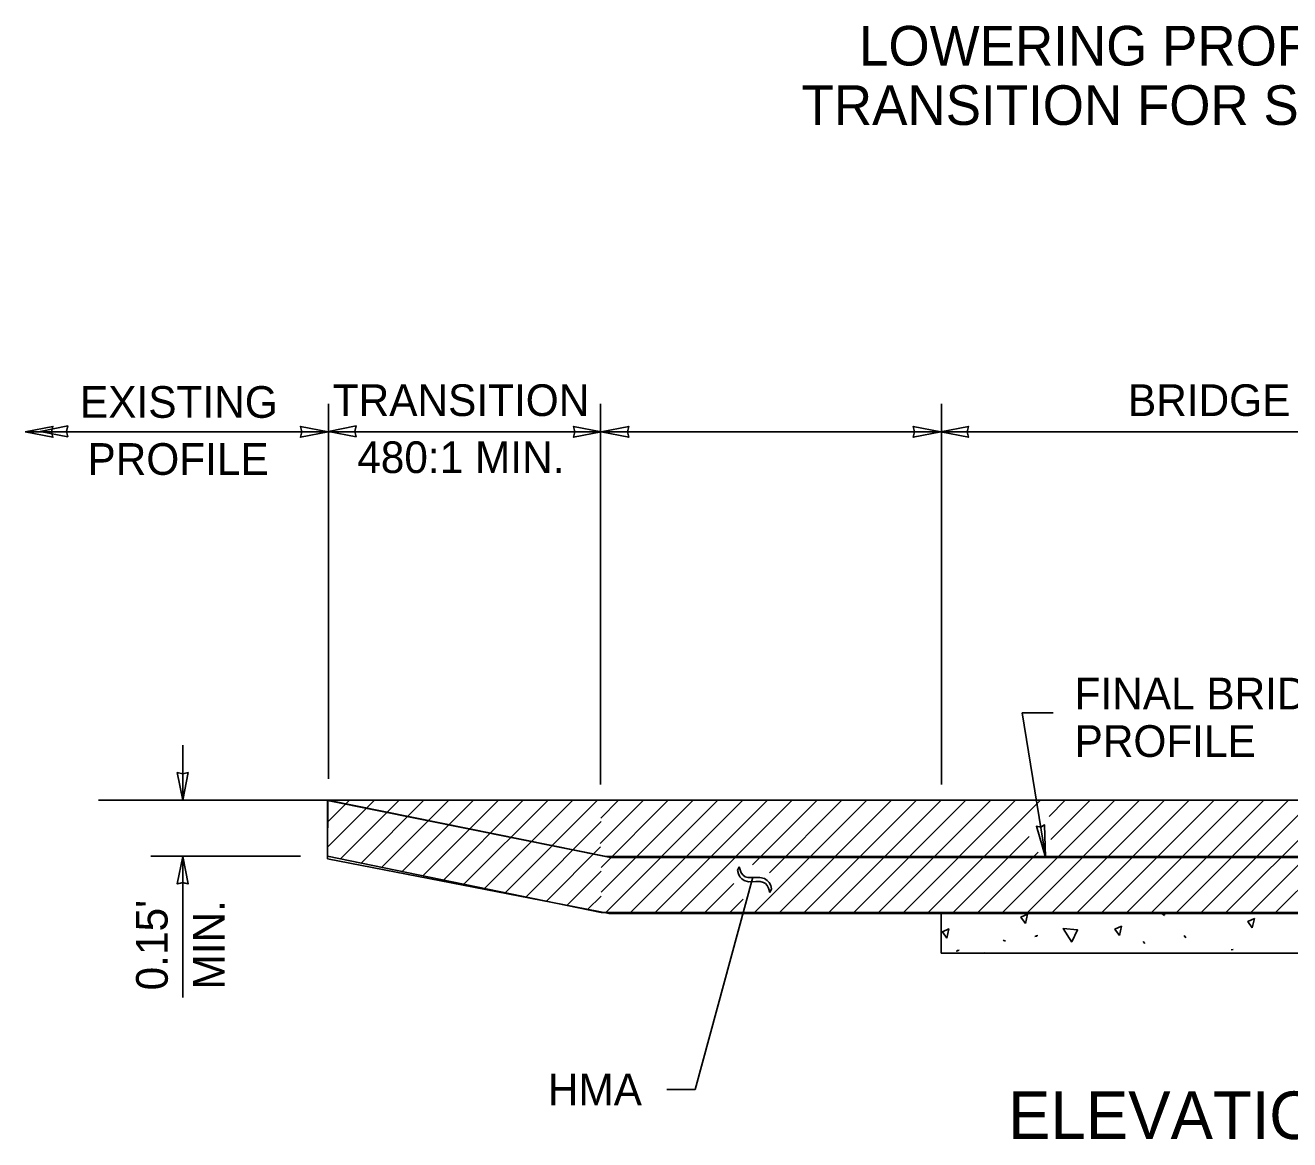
# Model space of a CAD drawing. Extents: x 99862 to 103151, y 100000 to 102076.
# Drawn here: x 101115 to 101753, y 100853 to 101416 of the extents above; entities that cross this region are included whole.
import ezdxf

# ---------------------------------------------------------------- set-up
doc = ezdxf.new("R2010")
doc.units = 0
for name, color, linetype in [('Level 10', 7, 'Continuous'), ('Level 14', 7, 'Continuous'), ('Level 15', 7, 'Continuous'), ('Level 16', 7, 'Continuous'), ('Level 20', 7, 'Continuous'), ('Level 4', 7, 'Continuous'), ('Level 5', 7, 'Continuous')]:
    doc.layers.add(name, color=color, linetype=linetype)

msp = doc.modelspace()

# ---------------------------------------------------------------- linework, layer by layer
at = {"layer": 'Level 10'}
for p, q in [((101408.1, 100995.99), (101267.47, 101024.37)), ((101408.1, 100995.99), (102017.05, 100995.99)), ((101405.56, 100967.72), (102017.05, 100967.72)), ((101577.33, 100947.17), (101577.33, 100967.17)), ((101690.02, 100966.21), (101688.79, 100967.17)), ((101690.12, 100967.17), (101690.05, 100966.35)), ((101624.61, 100955.63), (101625.63, 100955.69)), ((101625.17, 100955.96), (101626.2, 100956.02)), ((101700.84, 100954.93), (101700.02, 100956.06)), ((101585.45, 100948.53), (101586.47, 100948.6)), ((101608.58, 100953.69), (101609.76, 100953.17)), ((101680.11, 100951.97), (101679.28, 100953.1)), ((101723.8, 100948.9), (101724.82, 100948.96)), ((101584.89, 100948.2), (101585.91, 100948.27))]:
    msp.add_line(p, q, dxfattribs=at)
for points in [[(101267.47, 101024.37), (101267.42, 100996.06), (101405.56, 100967.72)], [(101577.33, 100967.17), (101849.57, 100967.17)], [(101619.85, 100962.15), (101617.62, 100965.41), (101620.89, 100966.8), (101619.85, 100962.15)], [(101734.45, 100959.97), (101732.23, 100963.22), (101735.5, 100964.62), (101734.45, 100959.97)], [(101580.12, 100954.72), (101577.9, 100957.98), (101581.17, 100959.37), (101580.12, 100954.72)], [(101643.29, 100952.72), (101638.94, 100959.66), (101646.21, 100958.91), (101643.36, 100952.84)], [(101667.31, 100956.11), (101665.09, 100959.36), (101668.36, 100960.76), (101667.31, 100956.11)], [(101849.57, 100947.17), (101577.33, 100947.17)], [(101598.74, 100947.17), (101599.14, 100947.27), (101599.13, 100947.17)]]:
    msp.add_lwpolyline(points, dxfattribs=at)
at = {"layer": 'Level 14'}
for p, q in [((101267.43, 101000.75), (101291.04, 101024.37)), ((101267.45, 101013.3), (101278.51, 101024.37)), ((101273.93, 100994.72), (101303.57, 101024.37)), ((101284.32, 100992.59), (101316.11, 101024.37)), ((101294.72, 100990.46), (101328.64, 101024.37)), ((101305.12, 100988.32), (101341.17, 101024.37)), ((101315.52, 100986.19), (101353.7, 101024.37)), ((101325.91, 100984.06), (101366.23, 101024.37)), ((101336.31, 100981.92), (101378.76, 101024.37)), ((101346.71, 100979.79), (101391.29, 101024.37)), ((101357.11, 100977.66), (101403.82, 101024.37)), ((101405.12, 101002.55), (101426.94, 101024.37)), ((101405.35, 101015.31), (101414.41, 101024.37)), ((101405.56, 100977.93), (101452, 101024.37)), ((101405.56, 100990.46), (101439.47, 101024.37)), ((101407.88, 100967.72), (101464.53, 101024.37)), ((101420.41, 100967.72), (101477.06, 101024.37)), ((101432.94, 100967.72), (101489.59, 101024.37)), ((101445.47, 100967.72), (101502.12, 101024.37)), ((101482.08, 100991.8), (101514.65, 101024.37)), ((101483.06, 100967.72), (101539.71, 101024.37)), ((101490.57, 100987.76), (101527.18, 101024.37)), ((101495.59, 100967.72), (101552.24, 101024.37)), ((101508.12, 100967.72), (101564.77, 101024.37)), ((101520.65, 100967.72), (101577.3, 101024.37)), ((101533.18, 100967.72), (101589.83, 101024.37)), ((101545.71, 100967.72), (101602.36, 101024.37)), ((101558.24, 100967.72), (101614.89, 101024.37)), ((101570.77, 100967.72), (101627.43, 101024.37)), ((101608.36, 100967.72), (101665.02, 101024.37)), ((101620.89, 100967.72), (101677.55, 101024.37)), ((101631.8, 101016.21), (101639.96, 101024.37)), ((101632.68, 101004.56), (101652.49, 101024.37)), ((101633.43, 100967.72), (101690.08, 101024.37)), ((101645.96, 100967.72), (101702.61, 101024.37)), ((101658.49, 100967.72), (101715.14, 101024.37)), ((101671.02, 100967.72), (101727.67, 101024.37)), ((101683.55, 100967.72), (101740.2, 101024.37)), ((101696.08, 100967.72), (101752.73, 101024.37)), ((101708.61, 100967.72), (101765.26, 101024.37)), ((101721.14, 100967.72), (101777.79, 101024.37)), ((101733.67, 100967.72), (101790.32, 101024.37)), ((101746.2, 100967.72), (101802.85, 101024.37)), ((101367.5, 100975.52), (101405.56, 101013.58)), ((101583.3, 100967.72), (101621.67, 101006.09)), ((101377.9, 100973.39), (101405.31, 101000.8)), ((101595.83, 100967.72), (101626.32, 100998.21)), ((101388.3, 100971.26), (101405.56, 100988.52)), ((101458, 100967.72), (101472.56, 100982.28)), ((101398.69, 100969.13), (101405.56, 100975.99)), ((101470.53, 100967.72), (101477.29, 100974.48))]:
    msp.add_line(p, q, dxfattribs=at)
at = {"layer": 'Level 15'}
for p, q in [((101267.86, 101224.56), (101267.86, 101035.25)), ((101405.2, 101224.56), (101405.2, 101032.3)), ((101577.48, 101224.56), (101577.48, 101032.3)), ((101577.48, 101210.38), (101405.2, 101210.38)), ((101633.93, 101068.49), (101618.17, 101068.49)), ((101629.99, 100995.95), (101618.17, 101068.49)), ((101194.23, 101024.38), (101194.23, 101052.24)), ((101194.23, 100924.78), (101194.23, 100996.03)), ((101475.21, 100990.77), (101474.41, 100989.05)), ((101474.41, 100989.05), (101474.9, 100987.18)), ((101474.9, 100987.18), (101475.61, 100985.75)), ((101476.38, 100987.66), (101475.21, 100990.77)), ((101477.27, 100986.48), (101476.38, 100987.66)), ((101482.13, 100985.61), (101453.14, 100878.31)), ((101475.61, 100985.75), (101476.57, 100984.66)), ((101476.57, 100984.66), (101477.84, 100983.86)), ((101478.31, 100985.74), (101477.27, 100986.48)), ((101477.84, 100983.86), (101479.98, 100983.25)), ((101479.62, 100985.38), (101478.31, 100985.74)), ((101481.8, 100985.39), (101479.62, 100985.38)), ((101479.98, 100983.25), (101483.66, 100983.34)), ((101485.77, 100985.41), (101481.8, 100985.39)), ((101483.66, 100983.34), (101485.95, 100983.34)), ((101488.13, 100984.78), (101485.77, 100985.41)), ((101485.95, 100983.34), (101487.63, 100982.92)), ((101487.63, 100982.92), (101488.64, 100982.27)), ((101489.47, 100983.93), (101488.13, 100984.78)), ((101488.64, 100982.27), (101489.44, 100981.35)), ((101489.44, 100981.35), (101490.13, 100979.94)), ((101490.5, 100982.79), (101489.47, 100983.93)), ((101491.2, 100981.33), (101490.5, 100982.79)), ((101491.59, 100979.59), (101491.2, 100981.33)), ((101490.13, 100979.94), (101490.79, 100977.86)), ((101490.79, 100977.86), (101491.59, 100979.59)), ((101453.14, 100878.31), (101438.74, 100878.31))]:
    msp.add_line(p, q, dxfattribs=at)
for points in [[(101114.75, 101210.38), (101128.68, 101207.65), (101128.03, 101210.38), (101128.68, 101213.11)], [(101122.24, 101210.63), (101136.17, 101207.89), (101135.53, 101210.63), (101136.17, 101213.36)], [(101267.63, 101210.38), (101253.7, 101207.65), (101254.35, 101210.38), (101253.7, 101213.11)], [(101267.86, 101210.63), (101281.8, 101207.89), (101281.15, 101210.63), (101281.8, 101213.36)], [(101405.56, 101210.38), (101391.62, 101207.65), (101392.27, 101210.38), (101391.62, 101213.11)], [(101405.56, 101210.38), (101419.49, 101207.65), (101418.84, 101210.38), (101419.49, 101213.11)], [(101577.14, 101210.38), (101563.21, 101207.65), (101563.85, 101210.38), (101563.21, 101213.11)], [(101577.14, 101210.38), (101591.07, 101207.65), (101590.43, 101210.38), (101591.07, 101213.11)], [(101194.23, 101024.38), (101196.96, 101038.31), (101194.23, 101037.67), (101191.49, 101038.31)], [(101629.97, 100995.57), (101625.38, 101011.24), (101627.59, 101010.82), (101629.56, 101011.89)], [(101194.23, 100996.05), (101196.96, 100982.12), (101194.23, 100982.76), (101191.49, 100982.12)], [(101194.23, 100996.03), (101196.96, 100982.09), (101194.23, 100982.74), (101191.49, 100982.09)]]:
    msp.add_lwpolyline(points, close=True, dxfattribs=at)
at = {"layer": 'Level 16'}
msp.add_lwpolyline([(101267.38, 100994.78), (101409.57, 100967.17), (102017.33, 100967.17), (102160.36, 100995.57), (102160.36, 101024.37), (102017.33, 100995.55), (101410.31, 100995.55), (101267.38, 101024.19), (101267.38, 100994.78)], dxfattribs=at)
at = {"layer": 'Level 4'}
for p, q in [((101114.75, 101210.38), (101267.86, 101210.38)), ((101267.86, 101210.38), (101405.2, 101210.38)), ((101852.64, 101210.38), (101577.48, 101210.38)), ((101178.23, 100996.07), (101253.73, 100996.07))]:
    msp.add_line(p, q, dxfattribs=at)
at = {"layer": 'Level 5'}
for p, q in [((101151.74, 101024.37), (101272.56, 101024.37)), ((101267.47, 101024.37), (102160.36, 101024.37))]:
    msp.add_line(p, q, dxfattribs=at)

# ---------------------------------------------------------------- texts
at = {"layer": 'Level 20'}
for s, height, p in [('LOWERING PROFILE AT BRIDGE ', 20, (101535.82, 101395.36)), ('TRANSITION FOR SKEWED BRIDGES', 20, (101506.78, 101365.36)), ('EXISTING ', 16, (101142.38, 101217.47)), ('TRANSITION ', 16, (101270.03, 101218.38)), ('BRIDGE', 16, (101671.65, 101218.38)), ('PROFILE', 16, (101146.15, 101188.67)), ('480:1 MIN.', 16, (101282.39, 101189.58)), ('HMA', 16, (101378.64, 100870.31)), ('ELEVATION', 24, (101611.1, 100853.32))]:
    msp.add_text(s, height=height, dxfattribs=at).set_placement(p)
for s, rotation, p in [('FINAL BRIDGE ', 360, (101644.68, 101070.26)), ('PROFILE', 360, (101644.68, 101046.26)), ("0.15'", 90.18164, (101186.72, 100928.4)), ('MIN.', 90.18164, (101215.52, 100928.82))]:
    msp.add_text(s, height=16, rotation=rotation, dxfattribs=at).set_placement(p)

doc.saveas('drawing.dxf')
